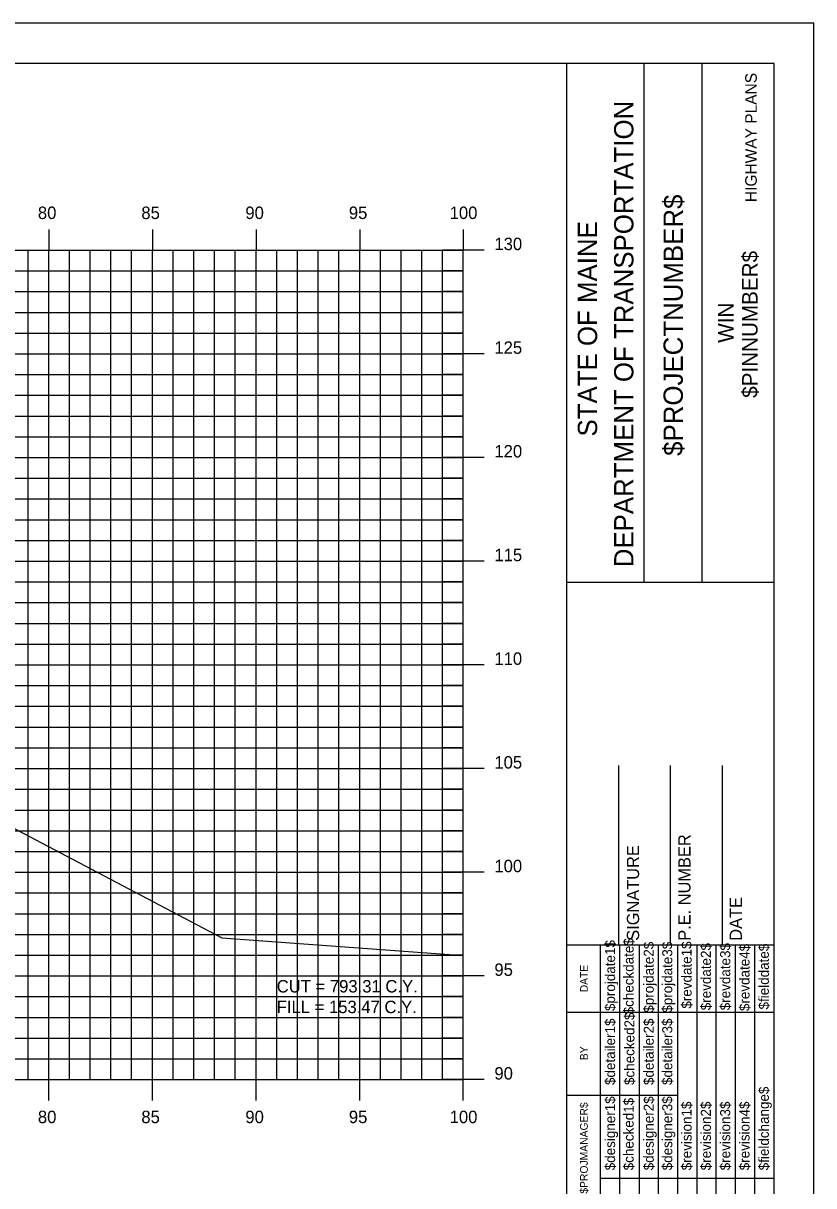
# Model space of a CAD drawing. Extents: x 850598 to 870284, y 366541 to 366651.
# Drawn here: x 852060.2 to 852098.3, y 366595.1 to 366651.2 of the extents above; entities that cross this region are included whole.
import ezdxf

# ---------------------------------------------------------------- set-up
doc = ezdxf.new("R2010")
doc.units = 0
for name, color, linetype in [('BORDER', 7, 'Continuous'), ('D_Text_Standard', 7, 'Continuous'), ('H_V ANNOTATION', 7, 'Continuous'), ('HIGHWAY_TITLE', 7, 'Continuous'), ('MAJOR', 7, 'Continuous'), ('MINOR', 7, 'Continuous'), ('PLOT BOUNDARY', 7, 'Continuous'), ('S_Roadway_Centerline', 7, 'Continuous')]:
    doc.layers.add(name, color=color, linetype=linetype)

msp = doc.modelspace()

# ---------------------------------------------------------------- linework, layer by layer
at = {"layer": 'BORDER'}
for p, q in [((852096.436, 366649.225), (851936.436, 366649.225)), ((852086.436, 366544.225), (852086.436, 366649.225)), ((852090.165, 366624.222), (852090.165, 366649.222)), ((852092.96, 366624.222), (852092.96, 366649.222)), ((852096.436, 366544.225), (852096.436, 366649.225)), ((852086.437, 366624.219), (852096.436, 366624.219)), ((852088.936, 366606.728), (852088.936, 366615.376)), ((852091.436, 366606.728), (852091.436, 366615.376)), ((852093.936, 366606.728), (852093.936, 366615.376)), ((852086.436, 366606.728), (852096.436, 366606.728))]:
    msp.add_line(p, q, dxfattribs=at)
for points in [[(852088.051, 366603.478), (852088.051, 366606.728)], [(852088.984, 366589.231), (852088.984, 366606.728)], [(852089.916, 366606.728), (852089.916, 366589.231)], [(852090.847, 366589.231), (852090.847, 366606.728)], [(852091.779, 366589.231), (852091.779, 366606.728)], [(852092.711, 366589.231), (852092.711, 366606.728)], [(852093.642, 366589.231), (852093.642, 366606.728)], [(852094.574, 366589.231), (852094.574, 366606.728)], [(852095.506, 366589.231), (852095.506, 366606.728)], [(852088.052, 366589.231), (852088.052, 366606.022)], [(852086.436, 366603.478), (852096.436, 366603.478)], [(852086.436, 366599.478), (852088.052, 366599.478)], [(852088.051, 366599.478), (852091.778, 366599.478)], [(852088.051, 366595.478), (852096.436, 366595.478)]]:
    msp.add_lwpolyline(points, dxfattribs=at)
at = {"layer": 'MAJOR'}
for p, q in [((852061.436, 366641.227), (852061.436, 366640.225)), ((852061.436, 366641.227), (852061.436, 366640.225)), ((852066.436, 366641.227), (852066.436, 366640.225)), ((852066.436, 366641.227), (852066.436, 366640.225)), ((852071.436, 366641.227), (852071.436, 366640.225)), ((852071.436, 366641.227), (852071.436, 366640.225)), ((852076.436, 366641.227), (852076.436, 366640.225)), ((852076.436, 366641.227), (852076.436, 366640.225)), ((852081.436, 366641.227), (852081.436, 366640.225)), ((852081.436, 366641.227), (852081.436, 366640.225)), ((851941.436, 366640.225), (852081.436, 366640.225)), ((851941.436, 366640.225), (852081.436, 366640.225)), ((851941.436, 366640.225), (852081.436, 366640.225)), ((851941.436, 366640.225), (852081.436, 366640.225)), ((852061.436, 366600.225), (852061.436, 366640.225)), ((852061.436, 366600.225), (852061.436, 366640.225)), ((852066.436, 366600.225), (852066.436, 366640.225)), ((852066.436, 366600.225), (852066.436, 366640.225)), ((852071.436, 366600.225), (852071.436, 366640.225)), ((852071.436, 366600.225), (852071.436, 366640.225)), ((852076.436, 366600.225), (852076.436, 366640.225)), ((852076.436, 366600.225), (852076.436, 366640.225)), ((852082.438, 366640.225), (852080.434, 366640.225)), ((852082.438, 366640.225), (852080.434, 366640.225)), ((852081.436, 366600.225), (852081.436, 366640.225)), ((852081.436, 366600.225), (852081.436, 366640.225)), ((852081.436, 366600.225), (852081.436, 366640.225)), ((852081.436, 366600.225), (852081.436, 366640.225)), ((851941.436, 366635.225), (852081.436, 366635.225)), ((851941.436, 366635.225), (852081.436, 366635.225)), ((852082.438, 366635.225), (852080.434, 366635.225)), ((852082.438, 366635.225), (852080.434, 366635.225)), ((851941.436, 366630.225), (852081.436, 366630.225)), ((851941.436, 366630.225), (852081.436, 366630.225)), ((852082.438, 366630.225), (852080.434, 366630.225)), ((852082.438, 366630.225), (852080.434, 366630.225)), ((851941.436, 366625.225), (852081.436, 366625.225)), ((851941.436, 366625.225), (852081.436, 366625.225)), ((852082.438, 366625.225), (852080.434, 366625.225)), ((852082.438, 366625.225), (852080.434, 366625.225)), ((851941.436, 366620.225), (852081.436, 366620.225)), ((851941.436, 366620.225), (852081.436, 366620.225)), ((852082.438, 366620.225), (852080.434, 366620.225)), ((852082.438, 366620.225), (852080.434, 366620.225)), ((851941.436, 366615.225), (852081.436, 366615.225)), ((851941.436, 366615.225), (852081.436, 366615.225)), ((852082.438, 366615.225), (852080.434, 366615.225)), ((852082.438, 366615.225), (852080.434, 366615.225)), ((851941.436, 366610.225), (852081.436, 366610.225)), ((851941.436, 366610.225), (852081.436, 366610.225)), ((852082.438, 366610.225), (852080.434, 366610.225)), ((852082.438, 366610.225), (852080.434, 366610.225)), ((851941.436, 366605.225), (852081.436, 366605.225)), ((851941.436, 366605.225), (852081.436, 366605.225)), ((852082.438, 366605.225), (852080.434, 366605.225)), ((852082.438, 366605.225), (852080.434, 366605.225)), ((851941.436, 366600.225), (852081.436, 366600.225)), ((851941.436, 366600.225), (852081.436, 366600.225)), ((851941.436, 366600.225), (852081.436, 366600.225)), ((851941.436, 366600.225), (852081.436, 366600.225)), ((852061.436, 366599.223), (852061.436, 366600.225)), ((852061.436, 366599.223), (852061.436, 366600.225)), ((852066.436, 366599.223), (852066.436, 366600.225)), ((852066.436, 366599.223), (852066.436, 366600.225)), ((852071.436, 366599.223), (852071.436, 366600.225)), ((852071.436, 366599.223), (852071.436, 366600.225)), ((852076.436, 366599.223), (852076.436, 366600.225)), ((852076.436, 366599.223), (852076.436, 366600.225)), ((852082.438, 366600.225), (852080.434, 366600.225)), ((852082.438, 366600.225), (852080.434, 366600.225)), ((852081.436, 366599.223), (852081.436, 366600.225)), ((852081.436, 366599.223), (852081.436, 366600.225))]:
    msp.add_line(p, q, dxfattribs=at)
at = {"layer": 'MINOR'}
for p, q in [((852060.436, 366600.225), (852060.436, 366640.225)), ((852060.436, 366600.225), (852060.436, 366640.225)), ((852062.436, 366600.225), (852062.436, 366640.225)), ((852062.436, 366600.225), (852062.436, 366640.225)), ((852063.436, 366600.225), (852063.436, 366640.225)), ((852063.436, 366600.225), (852063.436, 366640.225)), ((852064.436, 366600.225), (852064.436, 366640.225)), ((852064.436, 366600.225), (852064.436, 366640.225)), ((852065.436, 366600.225), (852065.436, 366640.225)), ((852065.436, 366600.225), (852065.436, 366640.225)), ((852067.436, 366600.225), (852067.436, 366640.225)), ((852067.436, 366600.225), (852067.436, 366640.225)), ((852068.436, 366600.225), (852068.436, 366640.225)), ((852068.436, 366600.225), (852068.436, 366640.225)), ((852069.436, 366600.225), (852069.436, 366640.225)), ((852069.436, 366600.225), (852069.436, 366640.225)), ((852070.436, 366600.225), (852070.436, 366640.225)), ((852070.436, 366600.225), (852070.436, 366640.225)), ((852072.436, 366600.225), (852072.436, 366640.225)), ((852072.436, 366600.225), (852072.436, 366640.225)), ((852073.436, 366600.225), (852073.436, 366640.225)), ((852073.436, 366600.225), (852073.436, 366640.225)), ((852074.436, 366600.225), (852074.436, 366640.225)), ((852074.436, 366600.225), (852074.436, 366640.225)), ((852075.436, 366600.225), (852075.436, 366640.225)), ((852075.436, 366600.225), (852075.436, 366640.225)), ((852077.436, 366600.225), (852077.436, 366640.225)), ((852077.436, 366600.225), (852077.436, 366640.225)), ((852078.436, 366600.225), (852078.436, 366640.225)), ((852078.436, 366600.225), (852078.436, 366640.225)), ((852079.436, 366600.225), (852079.436, 366640.225)), ((852079.436, 366600.225), (852079.436, 366640.225)), ((852080.436, 366600.225), (852080.436, 366640.225)), ((852080.436, 366600.225), (852080.436, 366640.225)), ((851941.436, 366639.225), (852081.436, 366639.225)), ((851941.436, 366639.225), (852081.436, 366639.225)), ((852081.436, 366639.225), (852080.434, 366639.225)), ((852081.436, 366639.225), (852080.434, 366639.225)), ((851941.436, 366638.225), (852081.436, 366638.225)), ((851941.436, 366638.225), (852081.436, 366638.225)), ((852081.436, 366638.225), (852080.434, 366638.225)), ((852081.436, 366638.225), (852080.434, 366638.225)), ((851941.436, 366637.225), (852081.436, 366637.225)), ((851941.436, 366637.225), (852081.436, 366637.225)), ((852081.436, 366637.225), (852080.434, 366637.225)), ((852081.436, 366637.225), (852080.434, 366637.225)), ((851941.436, 366636.225), (852081.436, 366636.225)), ((851941.436, 366636.225), (852081.436, 366636.225)), ((852081.436, 366636.225), (852080.434, 366636.225)), ((852081.436, 366636.225), (852080.434, 366636.225)), ((851941.436, 366634.225), (852081.436, 366634.225)), ((851941.436, 366634.225), (852081.436, 366634.225)), ((852081.436, 366634.225), (852080.434, 366634.225)), ((852081.436, 366634.225), (852080.434, 366634.225)), ((851941.436, 366633.225), (852081.436, 366633.225)), ((851941.436, 366633.225), (852081.436, 366633.225)), ((852081.436, 366633.225), (852080.434, 366633.225)), ((852081.436, 366633.225), (852080.434, 366633.225)), ((851941.436, 366632.225), (852081.436, 366632.225)), ((851941.436, 366632.225), (852081.436, 366632.225)), ((852081.436, 366632.225), (852080.434, 366632.225)), ((852081.436, 366632.225), (852080.434, 366632.225)), ((851941.436, 366631.225), (852081.436, 366631.225)), ((851941.436, 366631.225), (852081.436, 366631.225)), ((852081.436, 366631.225), (852080.434, 366631.225)), ((852081.436, 366631.225), (852080.434, 366631.225)), ((851941.436, 366629.225), (852081.436, 366629.225)), ((851941.436, 366629.225), (852081.436, 366629.225)), ((852081.436, 366629.225), (852080.434, 366629.225)), ((852081.436, 366629.225), (852080.434, 366629.225)), ((851941.436, 366628.225), (852081.436, 366628.225)), ((851941.436, 366628.225), (852081.436, 366628.225)), ((852081.436, 366628.225), (852080.434, 366628.225)), ((852081.436, 366628.225), (852080.434, 366628.225)), ((851941.436, 366627.225), (852081.436, 366627.225)), ((851941.436, 366627.225), (852081.436, 366627.225)), ((852081.436, 366627.225), (852080.434, 366627.225)), ((852081.436, 366627.225), (852080.434, 366627.225)), ((851941.436, 366626.225), (852081.436, 366626.225)), ((851941.436, 366626.225), (852081.436, 366626.225)), ((852081.436, 366626.225), (852080.434, 366626.225)), ((852081.436, 366626.225), (852080.434, 366626.225)), ((851941.436, 366624.225), (852081.436, 366624.225)), ((851941.436, 366624.225), (852081.436, 366624.225)), ((852081.436, 366624.225), (852080.434, 366624.225)), ((852081.436, 366624.225), (852080.434, 366624.225)), ((851941.436, 366623.225), (852081.436, 366623.225)), ((851941.436, 366623.225), (852081.436, 366623.225)), ((852081.436, 366623.225), (852080.434, 366623.225)), ((852081.436, 366623.225), (852080.434, 366623.225)), ((851941.436, 366622.225), (852081.436, 366622.225)), ((851941.436, 366622.225), (852081.436, 366622.225)), ((852081.436, 366622.225), (852080.434, 366622.225)), ((852081.436, 366622.225), (852080.434, 366622.225)), ((851941.436, 366621.225), (852081.436, 366621.225)), ((851941.436, 366621.225), (852081.436, 366621.225)), ((852081.436, 366621.225), (852080.434, 366621.225)), ((852081.436, 366621.225), (852080.434, 366621.225)), ((851941.436, 366619.225), (852081.436, 366619.225)), ((851941.436, 366619.225), (852081.436, 366619.225)), ((852081.436, 366619.225), (852080.434, 366619.225)), ((852081.436, 366619.225), (852080.434, 366619.225)), ((851941.436, 366618.225), (852081.436, 366618.225)), ((851941.436, 366618.225), (852081.436, 366618.225)), ((852081.436, 366618.225), (852080.434, 366618.225)), ((852081.436, 366618.225), (852080.434, 366618.225)), ((851941.436, 366617.225), (852081.436, 366617.225)), ((851941.436, 366617.225), (852081.436, 366617.225)), ((852081.436, 366617.225), (852080.434, 366617.225)), ((852081.436, 366617.225), (852080.434, 366617.225)), ((851941.436, 366616.225), (852081.436, 366616.225)), ((851941.436, 366616.225), (852081.436, 366616.225)), ((852081.436, 366616.225), (852080.434, 366616.225)), ((852081.436, 366616.225), (852080.434, 366616.225)), ((851941.436, 366614.225), (852081.436, 366614.225)), ((851941.436, 366614.225), (852081.436, 366614.225)), ((852081.436, 366614.225), (852080.434, 366614.225)), ((852081.436, 366614.225), (852080.434, 366614.225)), ((851941.436, 366613.225), (852081.436, 366613.225)), ((851941.436, 366613.225), (852081.436, 366613.225)), ((852081.436, 366613.225), (852080.434, 366613.225)), ((852081.436, 366613.225), (852080.434, 366613.225)), ((851941.436, 366612.225), (852081.436, 366612.225)), ((851941.436, 366612.225), (852081.436, 366612.225)), ((852081.436, 366612.225), (852080.434, 366612.225)), ((852081.436, 366612.225), (852080.434, 366612.225)), ((851941.436, 366611.225), (852081.436, 366611.225)), ((851941.436, 366611.225), (852081.436, 366611.225)), ((852081.436, 366611.225), (852080.434, 366611.225)), ((852081.436, 366611.225), (852080.434, 366611.225)), ((851941.436, 366609.225), (852081.436, 366609.225)), ((851941.436, 366609.225), (852081.436, 366609.225)), ((852081.436, 366609.225), (852080.434, 366609.225)), ((852081.436, 366609.225), (852080.434, 366609.225)), ((851941.436, 366608.225), (852081.436, 366608.225)), ((851941.436, 366608.225), (852081.436, 366608.225)), ((852081.436, 366608.225), (852080.434, 366608.225)), ((852081.436, 366608.225), (852080.434, 366608.225)), ((851941.436, 366607.225), (852081.436, 366607.225)), ((851941.436, 366607.225), (852081.436, 366607.225)), ((852081.436, 366607.225), (852080.434, 366607.225)), ((852081.436, 366607.225), (852080.434, 366607.225)), ((851941.436, 366606.225), (852081.436, 366606.225)), ((851941.436, 366606.225), (852081.436, 366606.225)), ((852081.436, 366606.225), (852080.434, 366606.225)), ((852081.436, 366606.225), (852080.434, 366606.225)), ((851941.436, 366604.225), (852081.436, 366604.225)), ((851941.436, 366604.225), (852081.436, 366604.225)), ((852081.436, 366604.225), (852080.434, 366604.225)), ((852081.436, 366604.225), (852080.434, 366604.225)), ((851941.436, 366603.225), (852081.436, 366603.225)), ((851941.436, 366603.225), (852081.436, 366603.225)), ((852081.436, 366603.225), (852080.434, 366603.225)), ((852081.436, 366603.225), (852080.434, 366603.225)), ((851941.436, 366602.225), (852081.436, 366602.225)), ((851941.436, 366602.225), (852081.436, 366602.225)), ((852081.436, 366602.225), (852080.434, 366602.225)), ((852081.436, 366602.225), (852080.434, 366602.225)), ((851941.436, 366601.225), (852081.436, 366601.225)), ((851941.436, 366601.225), (852081.436, 366601.225)), ((852081.436, 366601.225), (852080.434, 366601.225)), ((852081.436, 366601.225), (852080.434, 366601.225))]:
    msp.add_line(p, q, dxfattribs=at)
at = {"layer": 'PLOT BOUNDARY'}
msp.add_lwpolyline([(851928.343, 366541.166), (852098.343, 366541.166), (852098.343, 366651.166), (851928.343, 366651.166)], close=True, dxfattribs=at)
at = {"layer": 'S_Roadway_Centerline'}
msp.add_lwpolyline([(851941.436, 366624.619), (851946.198, 366624.56), (851968.596, 366625.699), (851986.828, 366626.579), (851995.049, 366627.725), (851996.482, 366628.04), (851997.32, 366628.156), (852000.545, 366628.561), (852002.937, 366628.672), (852015.281, 366629.309), (852017.599, 366629.322), (852031.301, 366629.429), (852032.808, 366628.857), (852036.025, 366627.589), (852038.86, 366626.482), (852043.581, 366622.758), (852051.848, 366616.471), (852055.701, 366614.478), (852069.779, 366607.058), (852081.436, 366606.213)], dxfattribs=at)

# ---------------------------------------------------------------- texts
at = {"layer": 'BORDER'}
for s, height, p in [('DEPARTMENT OF TRANSPORTATION', 0.93176, (852089.643, 366624.931)), ('$PROJECTNUMBER$', 0.93176, (852092.028, 366630.304)), ('STATE OF MAINE', 0.93176, (852087.892, 366631.237)), ('$PINNUMBER$', 0.74527, (852095.632, 366633.1)), ('WIN', 0.7453, (852094.473, 366635.755)), ('SIGNATURE', 0.5906, (852089.917, 366606.92)), ('P.E. NUMBER', 0.59055, (852092.397, 366606.92)), ('DATE', 0.5906, (852094.877, 366606.92)), ('$checkdate$', 0.48455, (852089.654, 366603.371)), ('$projdate1$', 0.48455, (852088.759, 366603.529)), ('$projdate2$', 0.48455, (852090.623, 366603.45)), ('$projdate3$', 0.48455, (852091.517, 366603.45)), ('$revdate1$', 0.4845, (852092.449, 366603.647)), ('$revdate2$', 0.4845, (852093.38, 366603.568)), ('$revdate3$', 0.4845, (852094.312, 366603.568)), ('$revdate4$', 0.4845, (852095.244, 366603.529)), ('$fielddate$', 0.48455, (852096.176, 366603.607)), ('DATE', 0.3714, (852087.441, 366604.434)), ('$detailer1$', 0.48455, (852088.759, 366599.963)), ('$checked2$', 0.4845, (852089.691, 366599.963)), ('$detailer2$', 0.48455, (852090.623, 366599.963)), ('$detailer3$', 0.48455, (852091.517, 366599.963)), ('BY', 0.3714, (852087.441, 366601.163)), ('$fieldchange$', 0.48455, (852096.176, 366595.851)), ('$designer1$', 0.48455, (852088.759, 366595.851)), ('$checked1$', 0.4845, (852089.654, 366595.851)), ('$designer2$', 0.48455, (852090.623, 366595.851)), ('$designer3$', 0.48455, (852091.517, 366595.851)), ('$revision1$', 0.48455, (852092.449, 366595.851)), ('$revision2$', 0.48455, (852093.38, 366595.851)), ('$revision3$', 0.48455, (852094.312, 366595.851)), ('$revision4$', 0.48455, (852095.244, 366595.851)), ('$PROJMANAGER$', 0.37275, (852087.441, 366594.723))]:
    msp.add_text(s, height=height, rotation=90, dxfattribs=at).set_placement(p)
at = {"layer": 'D_Text_Standard'}
for s, p in [('CUT = 793.31 C.Y.', (852072.436, 366604.425)), ('FILL = 153.47 C.Y.', (852072.436, 366603.429))]:
    msp.add_text(s, height=0.6, dxfattribs=at).set_placement(p)
at = {"layer": 'H_V ANNOTATION'}
for s, p in [('80', (852060.912, 366641.725)), ('85', (852065.904, 366641.725)), ('90', (852070.922, 366641.725)), ('95', (852075.914, 366641.725)), ('100', (852080.778, 366641.725)), ('130', (852082.936, 366640.225)), ('125', (852082.936, 366635.225)), ('120', (852082.936, 366630.225)), ('115', (852082.936, 366625.225)), ('110', (852082.936, 366620.225)), ('105', (852082.936, 366615.225)), ('100', (852082.936, 366610.225)), ('95', (852082.936, 366605.225)), ('90', (852082.936, 366600.225)), ('80', (852060.912, 366598.125)), ('85', (852065.904, 366598.125)), ('90', (852070.922, 366598.125)), ('95', (852075.914, 366598.125)), ('100', (852080.778, 366598.125))]:
    msp.add_text(s, height=0.6, dxfattribs=at).set_placement(p)
at = {"layer": 'HIGHWAY_TITLE'}
msp.add_text('HIGHWAY PLANS', height=0.55901, rotation=90, dxfattribs=at).set_placement((852095.595, 366642.541))

doc.saveas('drawing.dxf')
